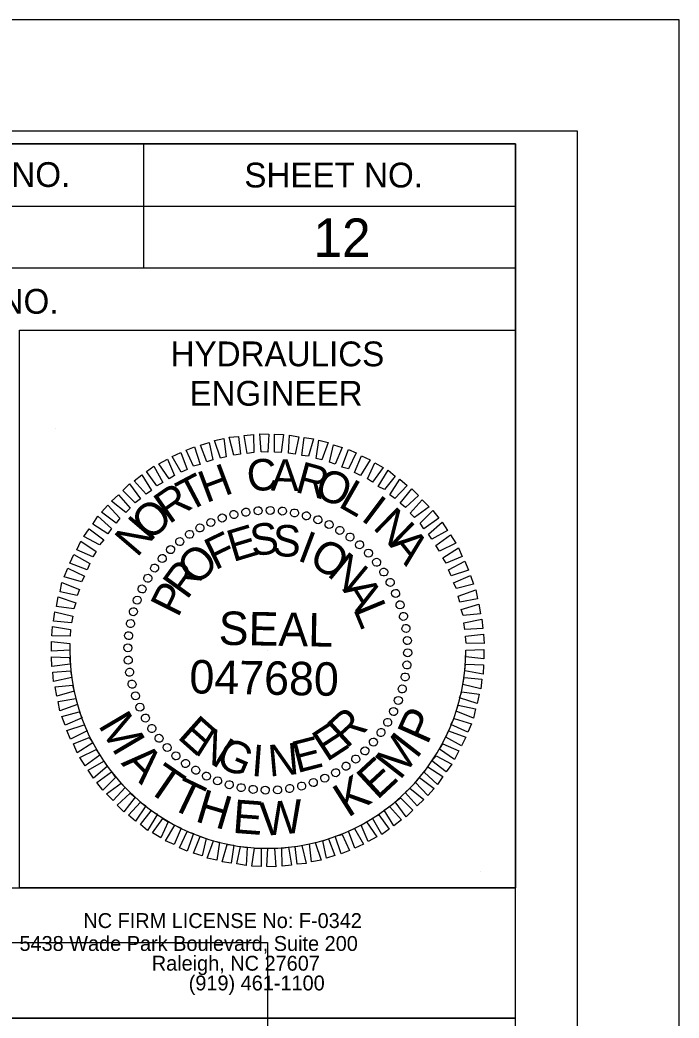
# Model space of a CAD drawing. Extents: x -130 to 890, y -29895 to -29235.
# Drawn here: x 810 to 889.8, y -29355.5 to -29234.8 of the extents above; entities that cross this region are included whole.
import ezdxf

# ---------------------------------------------------------------- set-up
doc = ezdxf.new("R2010")
doc.units = 0
for name, color, linetype in [('Old_Level_2', 7, 'Continuous'), ('Prop DSN Text', 7, 'Continuous'), ('Scratch_Level_0', 7, 'Continuous'), ('Sheet Block Title CELL', 7, 'Continuous'), ('Sheet Border Standard 30in CELL', 7, 'Continuous'), ('Sheet Cutting Line CELL', 7, 'Continuous'), ('Sheet Data Field CELL', 7, 'Continuous'), ('Sheet Plot Border Inside CELL', 7, 'Continuous'), ('Sheet Plot Border Outside CELL', 7, 'Continuous'), ('Sheet Profile CELL', 7, 'Continuous'), ('Sheet Sticker Exception Certification CELL', 7, 'Continuous')]:
    doc.layers.add(name, color=color, linetype=linetype)

msp = doc.modelspace()

# ---------------------------------------------------------------- linework, layer by layer
at = {"layer": 'Old_Level_2'}
for p, q in [((814.31, -29284.23), (814.31, -29284.23)), ((835.91, -29294.59), (835.91, -29294.59)), ((837.4, -29294.32), (837.4, -29294.32)), ((838.85, -29294.12), (838.85, -29294.12)), ((840.33, -29294.09), (840.33, -29294.09)), ((841.82, -29294.19), (841.82, -29294.19)), ((843.27, -29294.43), (843.27, -29294.43)), ((844.69, -29294.73), (844.69, -29294.73)), ((833.15, -29295.54), (833.15, -29295.54)), ((834.5, -29295), (834.5, -29295)), ((846.11, -29295.2), (846.11, -29295.2)), ((847.46, -29295.81), (847.46, -29295.81)), ((830.55, -29296.99), (830.55, -29296.99)), ((831.83, -29296.21), (831.83, -29296.21)), ((848.77, -29296.48), (848.77, -29296.48)), ((829.37, -29297.83), (829.37, -29297.83)), ((849.99, -29297.33), (849.99, -29297.33)), ((851.17, -29298.24), (851.17, -29298.24)), ((828.25, -29298.85), (828.25, -29298.85)), ((852.21, -29299.25), (852.21, -29299.25)), ((827.24, -29299.89), (827.24, -29299.89)), ((853.23, -29300.37), (853.23, -29300.37)), ((826.33, -29301.07), (826.33, -29301.07)), ((854.07, -29301.55), (854.07, -29301.55)), ((825.48, -29302.29), (825.48, -29302.29)), ((854.85, -29302.83), (854.85, -29302.83)), ((824.81, -29303.61), (824.81, -29303.61)), ((855.52, -29304.15), (855.52, -29304.15)), ((824.2, -29304.96), (824.2, -29304.96)), ((856.06, -29305.5), (856.06, -29305.5)), ((823.73, -29306.37), (823.73, -29306.37)), ((823.43, -29307.79), (823.43, -29307.79)), ((856.47, -29306.91), (856.47, -29306.91)), ((823.19, -29309.24), (823.19, -29309.24)), ((856.74, -29308.4), (856.74, -29308.4)), ((856.94, -29309.85), (856.94, -29309.85)), ((823.09, -29310.73), (823.09, -29310.73)), ((840.03, -29311.03), (840.03, -29311.03)), ((856.97, -29311.33), (856.97, -29311.33)), ((823.12, -29312.21), (823.12, -29312.21)), ((856.87, -29312.82), (856.87, -29312.82)), ((823.32, -29313.66), (823.32, -29313.66)), ((823.59, -29315.15), (823.59, -29315.15)), ((856.64, -29314.27), (856.64, -29314.27)), ((856.33, -29315.69), (856.33, -29315.69)), ((824, -29316.57), (824, -29316.57)), ((855.86, -29317.11), (855.86, -29317.11)), ((824.54, -29317.92), (824.54, -29317.92)), ((855.25, -29318.46), (855.25, -29318.46)), ((825.21, -29319.23), (825.21, -29319.23)), ((854.58, -29319.77), (854.58, -29319.77)), ((825.99, -29320.51), (825.99, -29320.51)), ((853.73, -29320.99), (853.73, -29320.99)), ((826.83, -29321.7), (826.83, -29321.7)), ((852.82, -29322.17), (852.82, -29322.17)), ((827.85, -29322.81), (827.85, -29322.81)), ((851.81, -29323.21), (851.81, -29323.21)), ((828.89, -29323.82), (828.89, -29323.82)), ((830.07, -29324.73), (830.07, -29324.73)), ((850.7, -29324.23), (850.7, -29324.23)), ((831.29, -29325.58), (831.29, -29325.58)), ((848.23, -29325.85), (848.23, -29325.85)), ((849.51, -29325.07), (849.51, -29325.07)), ((832.61, -29326.25), (832.61, -29326.25)), ((833.96, -29326.86), (833.96, -29326.86)), ((835.37, -29327.33), (835.37, -29327.33)), ((845.57, -29327.06), (845.57, -29327.06)), ((846.92, -29326.52), (846.92, -29326.52)), ((836.79, -29327.64), (836.79, -29327.64)), ((838.24, -29327.87), (838.24, -29327.87)), ((839.73, -29327.97), (839.73, -29327.97)), ((841.21, -29327.94), (841.21, -29327.94)), ((842.66, -29327.74), (842.66, -29327.74)), ((844.15, -29327.47), (844.15, -29327.47)), ((865.75, -29337.83), (865.75, -29337.83))]:
    msp.add_line(p, q, dxfattribs=at)
for points in [[(837.53, -29287.2), (837.16, -29285.04), (838.31, -29284.91), (838.34, -29287.1)], [(839.22, -29287.03), (839.05, -29284.84), (840.17, -29284.87), (840.03, -29287.07)], [(840.84, -29287.07), (840.84, -29284.87), (841.95, -29284.91), (841.65, -29287.1)], [(842.53, -29287.17), (842.66, -29284.98), (843.78, -29285.18), (843.34, -29287.3)], [(832.67, -29288.22), (831.9, -29286.19), (832.94, -29285.89), (833.38, -29287.98)], [(834.29, -29287.78), (833.58, -29285.65), (834.73, -29285.41), (835, -29287.61)], [(835.91, -29287.41), (835.37, -29285.25), (836.49, -29285.14), (836.72, -29287.3)], [(844.15, -29287.44), (844.45, -29285.28), (845.57, -29285.45), (844.96, -29287.54)], [(845.87, -29287.81), (846.21, -29285.62), (847.35, -29285.89), (846.58, -29287.98)], [(847.49, -29288.25), (848, -29286.16), (849.04, -29286.49), (848.2, -29288.49)], [(829.53, -29289.46), (828.45, -29287.57), (829.5, -29287.1), (830.28, -29289.16)], [(831.02, -29288.76), (830.14, -29286.8), (831.15, -29286.39), (831.86, -29288.55)], [(849.01, -29288.86), (849.78, -29286.73), (850.73, -29287.14), (849.78, -29289.09)], [(850.53, -29289.5), (851.37, -29287.51), (852.42, -29287.98), (851.27, -29289.87)], [(828.08, -29290.27), (826.83, -29288.45), (827.88, -29287.91), (828.72, -29289.87)], [(852.08, -29290.27), (852.99, -29288.35), (854, -29288.92), (852.72, -29290.68)], [(825.32, -29292.13), (823.86, -29290.51), (824.78, -29289.8), (825.96, -29291.69)], [(826.6, -29291.12), (825.35, -29289.4), (826.23, -29288.76), (827.34, -29290.71)], [(853.4, -29291.19), (854.58, -29289.23), (855.45, -29289.94), (854.14, -29291.59)], [(823.97, -29293.18), (822.48, -29291.69), (823.29, -29290.88), (824.61, -29292.7)], [(854.78, -29292.2), (856.03, -29290.34), (856.91, -29291.08), (855.42, -29292.67)], [(822.85, -29294.36), (821.13, -29292.97), (821.97, -29292.2), (823.39, -29293.82)], [(856.06, -29293.24), (857.45, -29291.49), (858.26, -29292.3), (856.7, -29293.75)], [(821.67, -29295.64), (819.92, -29294.32), (820.66, -29293.45), (822.14, -29295.03)], [(857.28, -29294.43), (858.73, -29292.84), (859.54, -29293.65), (857.78, -29294.97)], [(858.46, -29295.64), (860.01, -29294.12), (860.72, -29295.03), (858.93, -29296.32)], [(820.66, -29296.92), (818.84, -29295.78), (819.48, -29294.8), (821.1, -29296.28)], [(859.47, -29296.96), (861.12, -29295.54), (861.77, -29296.52), (859.88, -29297.6)], [(819.65, -29298.27), (817.76, -29297.26), (818.43, -29296.32), (820.19, -29297.67)], [(860.35, -29298.34), (862.14, -29297.06), (862.78, -29298.07), (860.82, -29299.02)], [(818.84, -29299.72), (816.91, -29298.88), (817.42, -29297.83), (819.24, -29299.08)], [(818.16, -29301.28), (816.07, -29300.5), (816.57, -29299.45), (818.5, -29300.53)], [(861.23, -29299.83), (863.12, -29298.64), (863.55, -29299.69), (861.63, -29300.47)], [(861.9, -29301.28), (863.89, -29300.26), (864.33, -29301.34), (862.24, -29302.02)], [(817.49, -29302.76), (815.39, -29302.15), (815.83, -29301.11), (817.86, -29302.05)], [(862.51, -29302.86), (864.57, -29301.99), (864.94, -29303.03), (862.85, -29303.57)], [(816.98, -29304.38), (814.89, -29303.94), (815.12, -29302.83), (817.25, -29303.67)], [(863.05, -29304.48), (865.21, -29303.71), (865.41, -29304.82), (863.28, -29305.19)], [(816.54, -29306), (814.45, -29305.73), (814.68, -29304.58), (816.81, -29305.29)], [(863.45, -29306.1), (865.58, -29305.46), (865.78, -29306.61), (863.66, -29306.81)], [(816.27, -29307.72), (814.11, -29307.52), (814.25, -29306.37), (816.44, -29306.91)], [(863.76, -29307.72), (865.95, -29307.25), (866.05, -29308.4), (863.89, -29308.53)], [(816.1, -29309.34), (813.91, -29309.28), (813.98, -29308.16), (816.17, -29308.53)], [(863.96, -29309.34), (866.15, -29309.07), (866.22, -29310.22), (864.03, -29310.15)], [(816.07, -29311.03), (813.87, -29311.13), (813.87, -29309.98), (816.07, -29310.22)], [(863.99, -29311.03), (866.19, -29310.93), (866.19, -29312.08), (863.99, -29311.84)], [(816.1, -29312.72), (813.91, -29312.99), (813.84, -29311.84), (816.03, -29311.91)], [(863.96, -29312.72), (866.15, -29312.79), (866.09, -29313.9), (863.89, -29313.53)], [(816.3, -29314.34), (814.11, -29314.81), (814.01, -29313.66), (816.17, -29313.53)], [(816.61, -29315.96), (814.48, -29316.6), (814.28, -29315.45), (816.41, -29315.25)], [(863.79, -29314.34), (865.95, -29314.54), (865.82, -29315.69), (863.62, -29315.15)], [(863.52, -29316.06), (865.61, -29316.33), (865.38, -29317.48), (863.25, -29316.77)], [(817.01, -29317.58), (814.85, -29318.35), (814.65, -29317.24), (816.78, -29316.87)], [(863.08, -29317.68), (865.17, -29318.12), (864.94, -29319.23), (862.81, -29318.39)], [(817.55, -29319.2), (815.49, -29320.08), (815.12, -29319.03), (817.22, -29318.49)], [(818.16, -29320.78), (816.17, -29321.8), (815.73, -29320.72), (817.82, -29320.04)], [(862.58, -29319.3), (864.67, -29319.91), (864.23, -29320.95), (862.2, -29320.01)], [(861.9, -29320.78), (863.99, -29321.56), (863.49, -29322.61), (861.56, -29321.53)], [(818.84, -29322.24), (816.95, -29323.42), (816.51, -29322.37), (818.43, -29321.59)], [(861.23, -29322.34), (863.15, -29323.18), (862.64, -29324.23), (860.82, -29322.98)], [(819.71, -29323.72), (817.92, -29325), (817.28, -29323.99), (819.24, -29323.05)], [(820.59, -29325.1), (818.94, -29326.52), (818.3, -29325.54), (820.19, -29324.46)], [(860.42, -29323.79), (862.31, -29324.8), (861.63, -29325.75), (859.88, -29324.4)], [(821.6, -29326.42), (820.05, -29327.94), (819.34, -29327.03), (821.13, -29325.75)], [(859.4, -29325.14), (861.23, -29326.29), (860.58, -29327.26), (858.96, -29325.78)], [(822.78, -29327.64), (821.33, -29329.22), (820.52, -29328.41), (822.28, -29327.1)], [(858.39, -29326.42), (860.15, -29327.74), (859.4, -29328.61), (857.92, -29327.03)], [(824, -29328.82), (822.62, -29330.57), (821.81, -29329.76), (823.36, -29328.31)], [(857.21, -29327.7), (858.93, -29329.09), (858.09, -29329.86), (856.67, -29328.24)], [(825.28, -29329.86), (824.03, -29331.72), (823.16, -29330.98), (824.64, -29329.39)], [(856.1, -29328.88), (857.58, -29330.37), (856.77, -29331.18), (855.45, -29329.36)], [(826.67, -29330.88), (825.48, -29332.83), (824.61, -29332.12), (825.92, -29330.47)], [(853.46, -29330.94), (854.71, -29332.66), (853.83, -29333.31), (852.72, -29331.35)], [(854.75, -29329.93), (856.2, -29331.55), (855.29, -29332.26), (854.1, -29330.37)], [(827.98, -29331.79), (827.07, -29333.71), (826.06, -29333.14), (827.34, -29331.38)], [(829.53, -29332.56), (828.69, -29334.55), (827.64, -29334.08), (828.79, -29332.19)], [(851.98, -29331.79), (853.23, -29333.61), (852.18, -29334.15), (851.34, -29332.19)], [(831.05, -29333.2), (830.28, -29335.33), (829.33, -29334.93), (830.28, -29332.97)], [(849.04, -29333.31), (849.92, -29335.26), (848.91, -29335.67), (848.2, -29333.51)], [(850.53, -29332.6), (851.61, -29334.49), (850.56, -29334.96), (849.78, -29332.9)], [(832.57, -29333.81), (832.07, -29335.9), (831.02, -29335.57), (831.86, -29333.58)], [(834.19, -29334.25), (833.85, -29336.44), (832.71, -29336.17), (833.48, -29334.08)], [(835.91, -29334.62), (835.61, -29336.78), (834.5, -29336.61), (835.1, -29334.52)], [(845.77, -29334.28), (846.48, -29336.41), (845.33, -29336.65), (845.06, -29334.45)], [(847.39, -29333.85), (848.16, -29335.87), (847.12, -29336.17), (846.68, -29334.08)], [(837.53, -29334.89), (837.4, -29337.09), (836.28, -29336.88), (836.72, -29334.76)], [(839.22, -29334.99), (839.22, -29337.19), (838.11, -29337.15), (838.41, -29334.96)], [(840.84, -29335.03), (841.01, -29337.22), (839.9, -29337.19), (840.03, -29334.99)], [(842.53, -29334.86), (842.9, -29337.02), (841.75, -29337.15), (841.72, -29334.96)], [(844.15, -29334.66), (844.69, -29336.82), (843.57, -29336.92), (843.34, -29334.76)]]:
    msp.add_lwpolyline(points, close=True, dxfattribs=at)
for centre, major_axis in [((834.52, -29295.02), (-0.158, 0.46)), ((835.93, -29294.6), (-0.118, 0.472)), ((837.38, -29294.31), (-0.076, 0.48)), ((838.85, -29294.14), (-0.034, 0.485)), ((840.33, -29294.1), (0.008, 0.486)), ((841.8, -29294.19), (0.051, 0.483)), ((843.26, -29294.41), (0.093, 0.477)), ((844.7, -29294.76), (0.134, 0.467)), ((846.1, -29295.23), (0.174, 0.454)), ((831.82, -29296.22), (-0.236, 0.425)), ((833.14, -29295.56), (-0.198, 0.444)), ((847.45, -29295.81), (0.213, 0.437)), ((848.75, -29296.52), (0.25, 0.417)), ((830.56, -29297), (-0.272, 0.403)), ((849.98, -29297.33), (0.286, 0.393)), ((828.27, -29298.85), (-0.338, 0.35)), ((829.38, -29297.87), (-0.306, 0.378)), ((851.14, -29298.25), (0.319, 0.367)), ((827.25, -29299.92), (-0.367, 0.319)), ((852.21, -29299.27), (0.35, 0.338)), ((826.33, -29301.08), (-0.393, 0.286)), ((853.19, -29300.38), (0.378, 0.306)), ((825.52, -29302.31), (-0.417, 0.25)), ((854.07, -29301.56), (0.403, 0.272)), ((824.81, -29303.61), (-0.437, 0.213)), ((854.84, -29302.82), (0.425, 0.236)), ((824.23, -29304.96), (-0.454, 0.174)), ((855.5, -29304.14), (0.444, 0.198)), ((856.04, -29305.52), (0.46, 0.158)), ((823.76, -29306.36), (-0.467, 0.134)), ((856.46, -29306.93), (0.472, 0.118)), ((823.41, -29307.8), (-0.477, 0.093)), ((856.75, -29308.38), (0.48, 0.076)), ((823.19, -29309.26), (-0.483, 0.051)), ((823.1, -29310.73), (-0.486, 0.008)), ((856.92, -29309.85), (0.485, 0.034)), ((856.96, -29311.33), (0.486, -0.008)), ((823.14, -29312.21), (-0.485, -0.034)), ((856.87, -29312.8), (0.483, -0.051)), ((823.31, -29313.68), (-0.48, -0.076)), ((856.65, -29314.26), (0.477, -0.093)), ((823.6, -29315.13), (-0.472, -0.118)), ((856.3, -29315.7), (0.467, -0.134)), ((824.02, -29316.54), (-0.46, -0.158)), ((824.56, -29317.92), (-0.444, -0.198)), ((855.83, -29317.1), (0.454, -0.174)), ((825.22, -29319.24), (-0.425, -0.236)), ((855.25, -29318.45), (0.437, -0.213)), ((826, -29320.5), (-0.403, -0.272)), ((854.54, -29319.75), (0.417, -0.25)), ((826.87, -29321.68), (-0.378, -0.306)), ((853.73, -29320.98), (0.393, -0.286)), ((827.85, -29322.79), (-0.35, -0.338)), ((852.81, -29322.14), (0.367, -0.319)), ((828.92, -29323.81), (-0.319, -0.367)), ((850.68, -29324.19), (0.306, -0.378)), ((851.79, -29323.21), (0.338, -0.35)), ((830.08, -29324.73), (-0.286, -0.393)), ((849.5, -29325.06), (0.272, -0.403)), ((831.31, -29325.54), (-0.25, -0.417)), ((832.61, -29326.25), (-0.213, -0.437)), ((846.92, -29326.5), (0.198, -0.444)), ((848.24, -29325.84), (0.236, -0.425)), ((833.96, -29326.83), (-0.174, -0.454)), ((835.36, -29327.3), (-0.134, -0.467)), ((836.8, -29327.65), (-0.093, -0.477)), ((838.26, -29327.87), (-0.051, -0.483)), ((842.68, -29327.75), (0.076, -0.48)), ((844.13, -29327.46), (0.118, -0.472)), ((845.54, -29327.04), (0.158, -0.46)), ((839.73, -29327.96), (-0.008, -0.486)), ((841.21, -29327.92), (0.034, -0.485))]:
    msp.add_ellipse(centre, major_axis=major_axis, ratio=0.999708, dxfattribs=at)
at = {"layer": 'Scratch_Level_0'}
msp.add_lwpolyline([(450, -29249.75), (750, -29249.75), (749.97, -29346.38), (840, -29346.38), (840, -29549.75), (450, -29549.75)], close=True, dxfattribs=at)
msp.add_arc((840.03, -29311.03), 23.96, 180, 360, dxfattribs=at)
at = {"layer": 'Sheet Block Title CELL'}
msp.add_lwpolyline([(749.97, -29339.78), (869.97, -29339.78), (869.97, -29355.53), (749.97, -29355.53)], close=True, dxfattribs=at)
at = {"layer": 'Sheet Border Standard 30in CELL'}
msp.add_line((870, -29264.78), (870, -29272.28), dxfattribs=at)
msp.add_lwpolyline([(810, -29272.28), (870, -29272.28), (870, -29339.78), (810, -29339.78)], close=True, dxfattribs=at)
at = {"layer": 'Sheet Cutting Line CELL'}
for p, q in [((889.8, -29234.75), (-130.2, -29234.75)), ((889.8, -29894.75), (889.8, -29234.75))]:
    msp.add_line(p, q, dxfattribs=at)
at = {"layer": 'Sheet Plot Border Inside CELL'}
msp.add_lwpolyline([(-122.4, -29881.28), (877.5, -29881.28), (877.5, -29248.22), (-122.4, -29248.22)], close=True, dxfattribs=at)
at = {"layer": 'Sheet Plot Border Outside CELL'}
msp.add_lwpolyline([(-130.2, -29894.75), (889.8, -29894.75), (889.8, -29234.75), (-130.2, -29234.75)], close=True, dxfattribs=at)
at = {"layer": 'Sheet Profile CELL'}
for p, q in [((825, -29249.78), (825, -29264.78)), ((749.97, -29257.28), (870, -29257.28))]:
    msp.add_line(p, q, dxfattribs=at)
for points in [[(870, -29249.75), (-30, -29249.75), (-30, -29879.75), (870, -29879.75)], [(749.97, -29249.75), (870, -29249.75), (870, -29264.78), (749.97, -29264.78)]]:
    msp.add_lwpolyline(points, close=True, dxfattribs=at)
at = {"layer": 'Sheet Sticker Exception Certification CELL'}
msp.add_line((749.97, -29355.53), (869.99, -29355.53), dxfattribs=at)

# ---------------------------------------------------------------- texts
at = {"layer": 'Old_Level_2'}
for s, height, rotation, p in [('H', 3.85, 20.6195, (832.57, -29293.24)), ('C', 3.81, 6.2199, (837.7, -29291.89)), ('A', 3.81, 359.0203, (840.37, -29291.69)), ('R', 3.83, 344.6211, (843.2, -29291.83)), ('T', 3.88, 27.8198, (830.38, -29294.36)), ('O', 3.86, 337.4212, (845.46, -29292.33)), ('R', 3.91, 35.0205, (828.08, -29295.84)), ('L', 3.89, 330.2209, (848.43, -29293.58)), ('O', 3.93, 42.2217, (825.75, -29297.94)), ('I', 3.92, 323.0201, (851.17, -29295.2)), ('N', 3.93, 315.8189, (852.62, -29296.25)), ('N', 3.93, 49.4235, (824.2, -29299.89)), ('E', 3.84, 16.6111, (835.81, -29300.37)), ('S', 3.81, 7.2556, (838.14, -29299.66)), ('S', 3.81, 357.9004, (840.57, -29299.62)), ('F', 3.88, 25.967, (833.65, -29301.38)), ('I', 3.86, 339.1896, (843.47, -29300.1)), ('A', 3.93, 308.6172, (854.61, -29298.24)), ('O', 3.89, 329.8335, (844.82, -29300.57)), ('O', 3.93, 44.6812, (831.42, -29303.37)), ('N', 3.92, 320.4766, (847.08, -29301.92)), ('R', 3.93, 54.0397, (830.24, -29305.02)), ('P', 3.9, 63.3989, (829.16, -29307.18)), ('A', 3.92, 301.7603, (849.01, -29303.67)), ('L', 3.88, 292.4009, (850.32, -29306)), ('SEAL', 4.049, 359, (834.06, -29310.36)), ('047680', 4.05, 359, (830.52, -29316.24)), ('M', 4.16, 300.5946, (819.43, -29320.08)), ('R', 3.93, 42.4814, (849.55, -29323.01)), ('P', 4.13, 65.9822, (859.34, -29322.58)), ('E', 3.93, 318.2769, (828.96, -29321.59)), ('E', 3.9, 33.1241, (847.15, -29324.6)), ('N', 3.9, 327.634, (830.99, -29323.42)), ('M', 4.18, 52.1673, (856.02, -29326.86)), ('G', 3.86, 336.9902, (833.55, -29324.94)), ('I', 3.81, 355.7012, (837.97, -29326.22)), ('N', 3.81, 5.0564, (840.23, -29326.32)), ('E', 3.83, 14.4118, (843.57, -29325.91)), ('A', 4.18, 314.4095, (822.18, -29324.74)), ('T', 4.16, 325.4865, (825.15, -29327.91)), ('E', 4.18, 42.8526, (853.25, -29329.24)), ('K', 4.15, 32.342, (849.71, -29331.35)), ('T', 4.12, 334.4865, (827.98, -29330.03)), ('H', 4.08, 343.4865, (831.1, -29331.69)), ('E', 4.05, 355.7279, (835.68, -29333.11)), ('W', 4.05, 5.0426, (839.31, -29333.52))]:
    msp.add_text(s, height=height, rotation=rotation, dxfattribs=at).set_placement(p)
at = {"layer": 'Prop DSN Text'}
for s, p in [('NC FIRM LICENSE No: F-0342', (817.71, -29344.64)), ('5438 Wade Park Boulevard, Suite 200', (809.98, -29347.41)), ('Raleigh, NC 27607', (825.99, -29349.8)), ('(919) 461-1100', (830.46, -29352.19))]:
    msp.add_text(s, height=1.8, rotation=0, dxfattribs=at).set_placement(p)
at = {"layer": 'Sheet Border Standard 30in CELL'}
for s, height, p in [('R/W SHEET NO.', 3.0001, (784.17, -29270.3)), ('HYDRAULICS', 3, (828.27, -29276.66)), ('ENGINEER', 3, (830.55, -29281.43))]:
    msp.add_text(s, height=height, rotation=0, dxfattribs=at).set_placement(p)
at = {"layer": 'Sheet Data Field CELL'}
msp.add_text('12', height=4.65, dxfattribs=at).set_placement((845.56, -29263.42))
at = {"layer": 'Sheet Profile CELL'}
for s, height, p in [('PROJECT REFERENCE NO.', 3.0001, (763.3, -29254.96)), ('SHEET NO.', 3, (837.19, -29255.02))]:
    msp.add_text(s, height=height, dxfattribs=at).set_placement(p)

doc.saveas('drawing.dxf')
